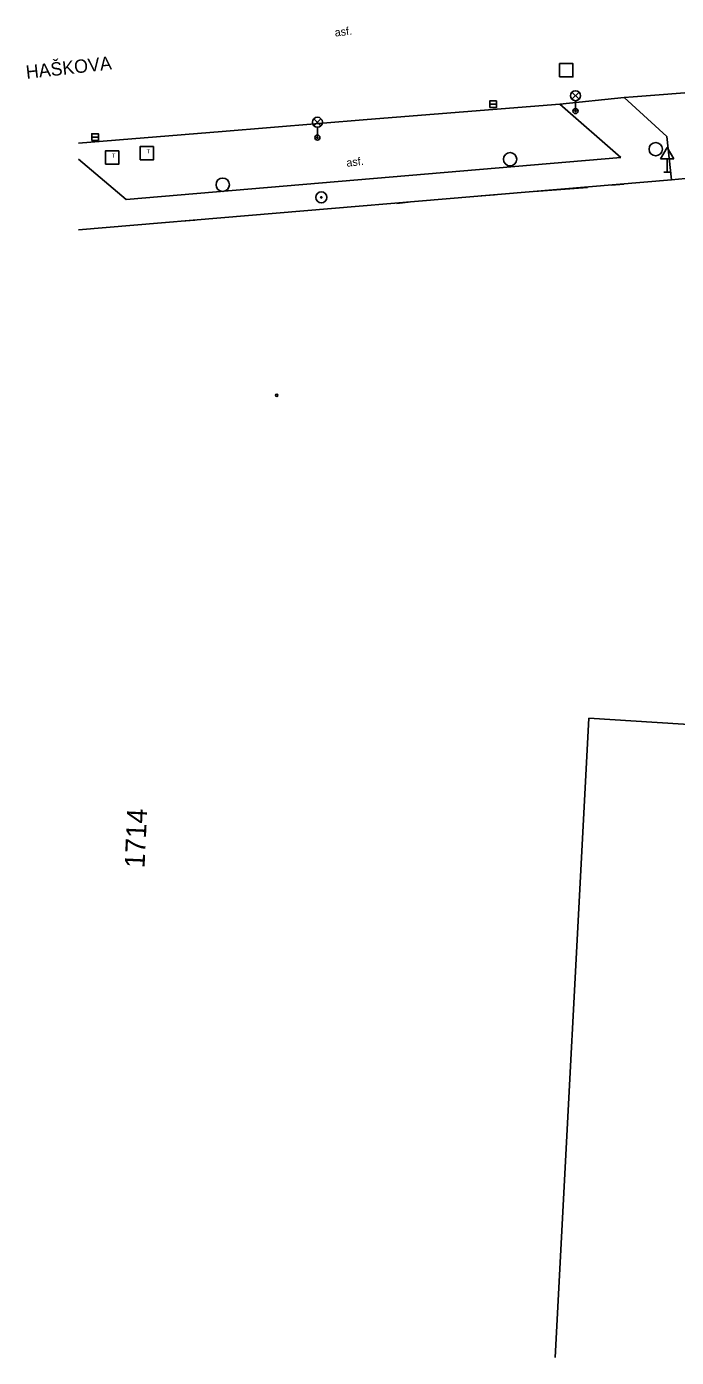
# Model space of a CAD drawing. Extents: x -642282 to -641982, y -1041678 to -1041427.
# Drawn here: x -642282.2 to -642233.5, y -1041677.6 to -1041577.8 of the extents above; entities that cross this region are included whole.
import ezdxf

# ---------------------------------------------------------------- set-up
doc = ezdxf.new("R2010")
doc.units = 0
for name, color, linetype in [('Budovy', 7, 'Continuous'), ('Budovy vstupy', 7, 'Continuous'), ('Pol_bod_pole', 7, 'Continuous'), ('Popis povrchů', 7, 'Continuous'), ('Popis ulice', 7, 'Continuous'), ('Popis ČP_ ČE', 7, 'Continuous'), ('Rozhraní ploch 1', 7, 'Continuous'), ('Rozhraní ploch 2', 7, 'Continuous'), ('Znaky doprava', 7, 'Continuous'), ('Znaky kanalizace', 7, 'Continuous'), ('Značky doprava', 7, 'Continuous'), ('Značky předmětů', 7, 'Continuous'), ('Šachta teplo', 7, 'Continuous'), ('Šachty ner_', 7, 'Continuous')]:
    doc.layers.add(name, color=color, linetype=linetype)

msp = doc.modelspace()

# ---------------------------------------------------------------- linework, layer by layer
at = {"layer": 'Budovy'}
for p, q in [((-642233.854, -1041589.321), (-642278.331, -1041593.078)), ((-642227.872, -1041588.766), (-642233.854, -1041589.321))]:
    msp.add_line(p, q, dxfattribs=at)
for points in [[(-642240.048, -1041629.696), (-642242.584, -1041677.619)], [(-642223.09, -1041630.76), (-642240.048, -1041629.696)]]:
    msp.add_lwpolyline(points, dxfattribs=at)
at = {"layer": 'Budovy vstupy'}
for p, q in [((-642237.438, -1041589.654), (-642238.351, -1041589.732)), ((-642247.123, -1041590.442), (-642248.137, -1041590.528)), ((-642240.154, -1041589.896), (-642244.156, -1041590.191)), ((-642253.611, -1041590.99), (-642254.446, -1041591.093)), ((-642269.618, -1041592.344), (-642270.642, -1041592.432))]:
    msp.add_line(p, q, dxfattribs=at)
at = {"layer": 'Pol_bod_pole'}
for radius in [0.412, 0.05]:
    msp.add_circle((-642260.12, -1041590.64), radius, dxfattribs=at)
at = {"layer": 'Rozhraní ploch 1'}
for p, q in [((-642225.323, -1041582.22), (-642236.723, -1041583.094)), ((-642237.663, -1041587.652), (-642242.228, -1041583.642)), ((-642274.766, -1041590.796), (-642237.663, -1041587.652)), ((-642278.331, -1041587.769), (-642274.766, -1041590.796))]:
    msp.add_line(p, q, dxfattribs=at)
msp.add_lwpolyline([(-642236.723, -1041583.094), (-642237.401, -1041583.152), (-642242.228, -1041583.642)], dxfattribs=at)
at = {"layer": 'Rozhraní ploch 2'}
for p, q in [((-642242.228, -1041583.642), (-642256.684, -1041584.798)), ((-642256.684, -1041584.798), (-642267.556, -1041585.713)), ((-642267.556, -1041585.713), (-642278.331, -1041586.582))]:
    msp.add_line(p, q, dxfattribs=at)
msp.add_lwpolyline([(-642233.854, -1041589.321), (-642234.202, -1041586.073), (-642237.401, -1041583.152)], dxfattribs=at)
at = {"layer": 'Znaky doprava'}
for p, q in [((-642241.315, -1041582.755), (-642240.785, -1041583.285)), ((-642241.315, -1041583.285), (-642240.785, -1041582.755)), ((-642241.05, -1041584.17), (-642241.05, -1041583.395)), ((-642260.675, -1041584.745), (-642260.145, -1041585.275)), ((-642260.675, -1041585.275), (-642260.145, -1041584.745)), ((-642260.41, -1041586.16), (-642260.41, -1041585.385))]:
    msp.add_line(p, q, dxfattribs=at)
for centre, radius in [((-642241.05, -1041583.02), 0.375), ((-642260.41, -1041585.01), 0.375), ((-642241.05, -1041584.17), 0.19), ((-642241.05, -1041584.17), 0.05), ((-642260.41, -1041586.16), 0.19), ((-642260.41, -1041586.16), 0.05)]:
    msp.add_circle(centre, radius, dxfattribs=at)
at = {"layer": 'Znaky kanalizace'}
for p, q in [((-642247.48, -1041583.66), (-642246.98, -1041583.66)), ((-642277.34, -1041586.12), (-642276.84, -1041586.12))]:
    msp.add_line(p, q, dxfattribs=at)
for points in [[(-642247.48, -1041583.91), (-642246.98, -1041583.91), (-642246.98, -1041583.41), (-642247.48, -1041583.41)], [(-642277.34, -1041586.37), (-642276.84, -1041586.37), (-642276.84, -1041585.87), (-642277.34, -1041585.87)]]:
    msp.add_lwpolyline(points, close=True, dxfattribs=at)
for centre in [(-642235.036, -1041587.029), (-642245.961, -1041587.785), (-642267.518, -1041589.691)]:
    msp.add_circle(centre, 0.5, dxfattribs=at)
at = {"layer": 'Značky doprava'}
for p, q in [((-642234.665, -1041587.754), (-642234.165, -1041586.904)), ((-642234.165, -1041586.904), (-642233.665, -1041587.754)), ((-642234.665, -1041587.754), (-642233.665, -1041587.754)), ((-642234.165, -1041588.754), (-642234.165, -1041587.754)), ((-642234.414, -1041588.754), (-642233.916, -1041588.754))]:
    msp.add_line(p, q, dxfattribs=at)
at = {"layer": 'Značky předmětů'}
msp.add_circle((-642263.469, -1041605.484), 0.0875, dxfattribs=at)
at = {"layer": 'Šachta teplo'}
for points in [[(-642276.32, -1041588.16), (-642275.32, -1041588.16), (-642275.32, -1041587.16), (-642276.32, -1041587.16)], [(-642273.72, -1041587.83), (-642272.72, -1041587.83), (-642272.72, -1041586.83), (-642273.72, -1041586.83)]]:
    msp.add_lwpolyline(points, close=True, dxfattribs=at)
at = {"layer": 'Šachty ner_'}
msp.add_lwpolyline([(-642242.25, -1041581.61), (-642241.25, -1041581.61), (-642241.25, -1041580.61), (-642242.25, -1041580.61)], close=True, dxfattribs=at)

# ---------------------------------------------------------------- texts
at = {"layer": 'Popis povrchů'}
for p in [(-642259.081, -1041578.586), (-642258.206, -1041588.35)]:
    msp.add_text('asf.', height=0.6, rotation=6.54773, dxfattribs=at).set_placement(p)
at = {"layer": 'Popis ulice'}
msp.add_text('HAŠKOVA', height=1, rotation=6.3457, dxfattribs=at).set_placement((-642282.227, -1041581.759))
at = {"layer": 'Popis ČP_ ČE'}
msp.add_text('1714', height=1.5, rotation=87.33703, dxfattribs=at).set_placement((-642273.384, -1041640.959))
at = {"layer": 'Šachta teplo'}
for p in [(-642275.82, -1041587.66), (-642273.22, -1041587.33)]:
    msp.add_text('T', height=0.3, dxfattribs=at).set_placement(p)

doc.saveas('drawing.dxf')
